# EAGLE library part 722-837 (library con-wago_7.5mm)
Serie 722, Federleiste mit abgewinkelten Einlötstiften / Series 722, Female connector with angled solder pins Polzahl / Pole No.: 7 Rastermaß / Pitch: 7.5 mm Bemessungsspannung / Rated Voltage: 630 V Nennstrom / Nominal Current: 12 A Lötstiftlänge: / Solder Pin Length: 5 mm Farbe / Color: lichtgrau / light gray Stand: 01.01.2012. Die jeweils aktuellen Daten zu diesem Artikel finden Sie in unserem Produktkatalog, den Sie unter www.wago.com einsehen können. As of: 01/01/2012. Please find the newest data for this article in our product catalogue, which can be viewed under www.wago.com.
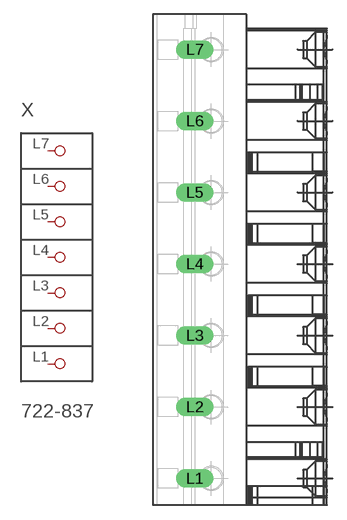
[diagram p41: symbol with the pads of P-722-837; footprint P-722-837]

Designator prefix X

## 722-837  [P-722-837]
L1  P1
L2  P2
L3  P3
L4  P4
L5  P5
L6  P6
L7  P7

## Footprint P-722-837 (pad centres in mm)
drill 1.3 long: L1 -5.007,-22.95; L2 -5.007,-15.45; L3 -5.007,-7.95; L4 -5.007,-0.45; L5 -5.007,7.05; L6 -5.007,14.55; L7 -5.007,22.05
